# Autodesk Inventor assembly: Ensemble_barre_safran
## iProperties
Shininess: 64.0
Length Units: 11269
Angle Units: 11279
Time Units: 11290
Mass Units: 11283
Length Display Precision: 3
Angle Display Precision: 2
Compacted: True
Created: 2004-06
Part Number: Ensemble_barre_safran
Document SubType Name: Assembly
Designer: David
Density: 0.0
Volumn: 0.0
Area: 0.0
PropertySet Name: Model Information
Control State: 0
Master: False
Checked Out: False
Author: David
